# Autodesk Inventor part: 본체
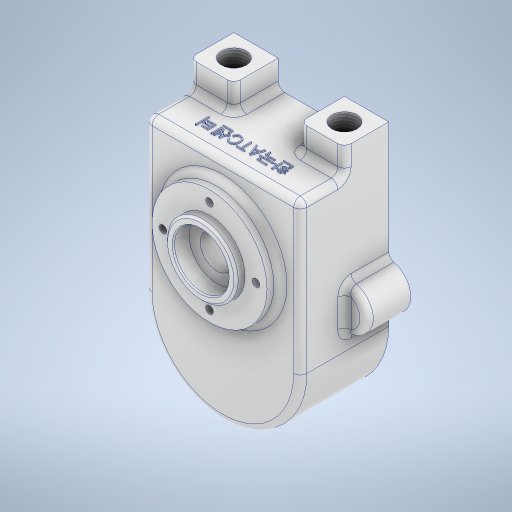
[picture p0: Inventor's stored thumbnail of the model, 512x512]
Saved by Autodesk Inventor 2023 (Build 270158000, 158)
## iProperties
Created: 2024-03
Part Number: 본체
Material: 알루미늄 6061
Document SubType Name: Modeling
Designer: asung
Density: 2.7 g/cm^3
Appearance: 알루미늄 - 평지
Author: asung
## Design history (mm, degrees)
sketch "스케치1" dims "d0" = 70
  geometry: L1 (0, 0)-(68, 0); L2 (35, 0)-(35, 68); L3 (35, 68)-(-35, 68); L4 (-35, 68)-(-35, 0); 3 further points
  constraints: 8 end point, 1 coincident, 1 horizontal, 1 horizontal alignment, 1 midpoint, 1 parallel, 1 perpendicular, 1 vertical alignment, 3 other
  dimensions: "d3" = 70 distance between parallel lines of L2 L4; "d4" = 68 distance of L2.start L2.end; "d5" = 68 distance from line of L4.end L3
extrude "돌출1" new body sketch "스케치1" distance "d6" = 40; taper "d7" = 0 deg
sketch "스케치2"
  geometry: L1 (-35, 68)-(-35, 0) reference; L2 (35, 0)-(35, 68) reference; L3 (35, 68)-(-35, 68) reference; C1 r 26 at (0, 33); A1 r 35 centre (0, 0) between (-35, 0) and (35, 0) reference; 2 further points
  constraints: 1 centre point, 1 midpoint, 1 vertical alignment
  dimensions: "d8" = 35 distance of point (0, 68) C1.centre; "d9" = 52 diameter of C1
extrude "돌출2" join sketch "스케치2" distance "d10" = 6; taper "d11" = 0 deg
sketch "스케치3"
  geometry: C1 r 26 at (0, 0) reference; C2 r 16 at (0, 0); 1 further point
  constraints: 1 centre point, 1 coincident
  dimensions: "d12" = 32 diameter of C2
extrude "돌출3" join sketch "스케치3" distance "d13" = 4; taper "d14" = 0 deg
sketch "스케치4"
  geometry: L1 (35, 68)-(35, 0) reference; L2 (-35, 68)-(35, 68) reference; L3 (-35, 0)-(-35, 68) reference; L4 (-15, 68)-(-15, 80); L5 (-15, 80)-(-35, 80); L6 (-35, 80)-(-35, 68); L7 (15, 68)-(15, 80); L8 (15, 80)-(35, 80); L9 (35, 80)-(35, 68); C1 r 29 at (0, 33) reference; A1 r 35 centre (0, 0) between (-35, 0) and (35, 0) reference; 1 further point
  constraints: 12 end point, 3 point on line, 2 horizontal, 2 parallel, 2 vertical
  dimensions: "d16" = 30 distance between parallel lines of L7 L4; "d17" = 20 distance of L7.end L8.end; "d18" = 12 distance between parallel lines of L2 L8
extrude "돌출4" join sketch "스케치4" distance "d19" = 20; taper "d20" = 0 deg
fillet "모깎기2" dims "d21" = 3
fillet "모깎기3" dims "d22" = 3
sketch "스케치5"
  geometry: L1 (0, 0)-(0, 33); L2 (-14, 11.314)-(-14, 21.686); L3 (14, 11.314)-(14, 21.686); C1 r 16 at (0, 33) reference; A1 r 18 centre (0, 33) between (14, 21.686) and (-14, 21.686); A2 r 18 centre (0, 0) between (-14, 11.314) and (14, 11.314); 1 further point
  constraints: 6 end point, 4 point on circle, 2 centre point, 2 coincident, 2 parallel, 1 vertical
  dimensions: "d26" = 33 distance of L1.start L1.end; "d30" = 36 diameter of A1; "d31" = 36 diameter of A2; "d32" = 28 distance between parallel lines of L3 L2; "d33" = 10.37258 distance of L3.start L3.end
extrude "돌출5" cut sketch "스케치5" distance "d34" = 20; taper "d35" = 0 deg
sketch "스케치6"
  geometry: L1 (-14, 11.314)-(-14, 21.686) reference; L2 (14, 21.686)-(14, 11.314) reference; L3 (35, 80)-(35, 0) reference; L4 (35, 80)-(15, 80) reference; L5 (15, 80)-(15, 71) reference; L6 (-12, 68)-(12, 68) reference; L7 (-15, 71)-(-15, 80) reference; L8 (-15, 80)-(-35, 80) reference; L9 (-35, 0)-(-35, 80) reference; C1 r 10 at (-35, 16.5); C2 r 10 at (35, 16.5); A1 r 18 centre (0, 33) between (14, 21.686) and (-14, 21.686) reference; A2 r 18 centre (0, 0) between (-14, 11.314) and (14, 11.314) reference; A3 r 3 centre (12, 71) between (12, 68) and (15, 71) reference; A4 r 3 centre (-12, 71) between (-15, 71) and (-12, 68) reference; A5 r 35 centre (0, 0) between (-35, 0) and (35, 0) reference; 7 further points
  constraints: 2 centre point, 2 horizontal alignment, 2 midpoint, 2 point on line
  dimensions: "d36" = 10 radius of C1; "d37" = 10 radius of C2
extrude "돌출6" join sketch "스케치6" distance "d38" = 20; taper "d39" = 0 deg
fillet "모깎기4" dims "d40" = 3
sketch "스케치7"
  geometry: A1 r 18 centre (0, 33) between (14, 21.686) and (-14, 21.686) reference; 2 further points
  constraints: 1 coincident
hole "구멍1" sketch "스케치7" at (0, 33) diameter "d41" = 15; stored, may be unused: countersink angle "d45" = 90 deg, drill point angle "d47" = 0 deg; dims "d42" = 8, "d43" = 20, "d44" = 10, "d46" = 40
sketch "스케치8"
  geometry: A1 r 18 centre (0, 0) between (-14, 11.314) and (14, 11.314) reference; 2 further points
  constraints: 1 coincident
hole "구멍2" sketch "스케치8" at (0, 0) diameter "d48" = 20; stored, may be unused: countersink angle "d52" = 90 deg, drill point angle "d54" = 0 deg; dims "d49" = 6, "d50" = 20, "d51" = 10, "d53" = 10
chamfer "모따기1" distance "d55" = 1; stored, may be unused: second distance "d56" = 2, angle "d57" = 45 deg
sketch "스케치9"
  geometry: 1 further point
node "작업 평면2"
sketch "스케치11"
  geometry: C1 r 13 at (0, 0) reference; 2 further points
  constraints: 1 coincident
hole "구멍3" sketch "스케치11" at (0, 0) diameter "d63" = 25; stored, may be unused: countersink angle "d67" = 90 deg, drill point angle "d69" = 0 deg; dims "d64" = 6, "d65" = 4, "d66" = 2, "d68" = 7.3
sketch "스케치12" dims "d73" = 42
  geometry: C1 r 16 at (0, 0) reference; C2 r 26 at (0, 0) reference; 3 further points
  constraints: 2 vertical alignment, 1 coincident, 2 other
hole "구멍4" sketch "스케치12" at (0, 21) diameter "d74" = 3.45873; stored, may be unused: countersink angle "d78" = 90 deg, drill point angle "d80" = 118 deg; dims "d75" = 8, "d76" = 4, "d77" = 2, "d79" = 10
sketch "스케치13"
  geometry: A1 r 10 centre (35, 16.5) between (37.308, 6.77) and (37.308, 26.23) reference; A2 r 10 centre (-35, 16.5) between (-37.308, 26.23) and (-37.308, 6.77) reference; 3 further points
  constraints: 2 coincident
hole "구멍5" sketch "스케치13" at (35, 16.5), (-35, 16.5) diameter "d84" = 4.45873; stored, may be unused: countersink angle "d88" = 90 deg, drill point angle "d90" = 118 deg; dims "d85" = 10, "d86" = 4, "d87" = 2, "d89" = 12
sketch "스케치14"
  geometry: L1 (-14, 11.314)-(-14, 21.686) reference; L2 (14, 21.686)-(14, 11.314) reference; L3 (35, 80)-(35, 29.149) reference; L4 (35, 80)-(15, 80) reference; L5 (15, 80)-(15, 71) reference; L6 (-12, 68)-(12, 68) reference; L7 (-15, 71)-(-15, 80) reference; L8 (-15, 80)-(-35, 80) reference; L9 (-35, 29.149)-(-35, 80) reference; L10 (-35, 0)-(-35, 3.851) reference; L11 (35, 3.851)-(35, 0) reference; C1 r 2.229 at (35, 16.5) reference; C2 r 2.229 at (-35, 16.5) reference; A1 r 18 centre (0, 33) between (14, 21.686) and (-14, 21.686) reference; A2 r 18 centre (0, 0) between (-14, 11.314) and (14, 11.314) reference; A3 r 3 centre (12, 71) between (12, 68) and (15, 71) reference; A4 r 3 centre (-12, 71) between (-15, 71) and (-12, 68) reference; A5 r 3 centre (-38, 29.149) between (-37.308, 26.23) and (-35, 29.149) reference; A6 r 10 centre (-35, 16.5) between (-37.308, 26.23) and (-37.308, 6.77) reference; A7 r 3 centre (-38, 3.851) between (-35, 3.851) and (-37.308, 6.77) reference; A8 r 35 centre (0, 0) between (-35, 0) and (35, 0) reference; A9 r 3 centre (38, 3.851) between (37.308, 6.77) and (35, 3.851) reference; A10 r 10 centre (35, 16.5) between (37.308, 6.77) and (37.308, 26.23) reference; A11 r 3 centre (38, 29.149) between (35, 29.149) and (37.308, 26.23) reference; 3 further points
  constraints: 2 vertical alignment
  dimensions: "d91" = 26 distance of A1.centre point (0, 59); "d92" = 26 distance of point (0, 0) point (0, -26)
hole "구멍6" sketch "스케치14" at (0, 59), (0, -26) diameter "d93" = 4.45873; stored, may be unused: countersink angle "d97" = 90 deg, drill point angle "d99" = 118 deg; dims "d94" = 10, "d95" = 4, "d96" = 2, "d98" = 12
sketch "스케치15"
  geometry: L1 (70, -20)-(53, -20) reference; L2 (70, 0)-(70, -20) reference; L3 (50, 0)-(70, 0) reference; L4 (50, 0)-(50, -17) reference; L5 (20, 0)-(20, -17) reference; L6 (0, 0)-(20, 0) reference; L7 (0, 0)-(0, -20) reference; L8 (17, -20)-(0, -20) reference; A1 r 3 centre (53, -17) between (50, -17) and (53, -20) reference; A2 r 3 centre (17, -17) between (17, -20) and (20, -17) reference; 3 further points
  constraints: 1 horizontal alignment
  dimensions: "d100" = 50 distance of point (60, -10) point (10, -10); "d101" = 10 distance from line of point (10, -10) L7; "d102" = 10 distance from line of L6 point (10, -10)
hole "구멍7" sketch "스케치15" at (10, -10), (60, -10) diameter "d103" = 10.5; stored, may be unused: countersink angle "d109" = 90 deg, drill point angle "d111" = 118 deg; dims "d104" = 11, "d105" = 0.62479, "d106" = 10.589, "d107" = 4, "d108" = 2, "d110" = 16
node "작업 평면1"
sketch "스케치17"
  geometry: L1 (-14, 21.686)-(-14, 11.314) reference; L2 (14, 11.314)-(14, 21.686) reference; L3 (-12, 68)-(12, 68) reference; L4 (15, 71)-(15, 80) reference; L5 (15, 80)-(19.362, 80) reference; L6 (19.362, 80)-(19.705, 69) reference; L7 (19.705, 69)-(19.75, 69) reference; L8 (19.75, 69)-(19.75, 64) reference; L9 (19.75, 64)-(25, 60.845) reference; L10 (25, 60.845)-(30.25, 64) reference; L11 (30.25, 64)-(30.25, 69) reference; L12 (30.25, 69)-(30.295, 69) reference; L13 (30.295, 69)-(30.638, 80) reference; L14 (30.638, 80)-(35, 80) reference; L15 (35, 80)-(35, 29.149) reference; L16 (35, 3.851)-(35, 0) reference; L17 (-35, 0)-(-35, 3.851) reference; L18 (-35, 29.149)-(-35, 80) reference; L19 (-35, 80)-(-30.638, 80) reference; L20 (-30.638, 80)-(-30.295, 69) reference; L21 (-30.295, 69)-(-30.25, 69) reference; L22 (-30.25, 69)-(-30.25, 64) reference; L23 (-30.25, 64)-(-25, 60.845) reference; L24 (-25, 60.845)-(-19.75, 64) reference; L25 (-19.75, 64)-(-19.75, 69) reference; L26 (-19.75, 69)-(-19.706, 69) reference; L27 (-19.706, 69)-(-19.362, 80) reference; L28 (-19.362, 80)-(-15, 80) reference; L29 (-15, 80)-(-15, 71) reference; L30 (-14, 11.314)-(-14, 21.686) reference; L31 (-19.75, 64)-(-30.25, 64) reference; L32 (-30.25, 64)-(-19.75, 64); L33 (25, 60.845)-(19.75, 64) reference; L34 (-25, 64)-(-25, 24.5); L35 (-14, 16.5)-(-17, 16.5); L36 (14, 21.686)-(14, 11.314) reference; L37 (19.75, 64)-(30.25, 64); L38 (25, 64)-(25, 24.5); L39 (14, 16.5)-(17, 16.5); L40 (28, 64)-(28, 24.5); L41 (17, 13.5)-(14, 13.5); L42 (22, 64)-(22, 24.5); L43 (17, 19.5)-(14, 19.5); L44 (-22, 64)-(-22, 24.5); L45 (-17, 19.5)-(-14, 19.5); L46 (-28, 64)-(-28, 24.5); L47 (-17, 13.5)-(-14, 13.5); C1 r 2.229 at (0, 59) reference; C2 r 2.229 at (0, -26) reference; C3 r 2.229 at (35, 16.5) reference; C4 r 2.229 at (-35, 16.5) reference; A1 r 18 centre (0, 0) between (-14, 11.314) and (14, 11.314) reference; A2 r 18 centre (0, 33) between (14, 21.686) and (-14, 21.686) reference; A3 r 3 centre (-12, 71) between (-15, 71) and (-12, 68) reference; A4 r 3 centre (12, 71) between (12, 68) and (15, 71) reference; A5 r 3 centre (38, 29.149) between (35, 29.149) and (37.308, 26.23) reference; A6 r 10 centre (35, 16.5) between (37.308, 6.77) and (37.308, 26.23) reference; A7 r 3 centre (38, 3.851) between (37.308, 6.77) and (35, 3.851) reference; A8 r 35 centre (0, 0) between (-35, 0) and (35, 0) reference; A9 r 3 centre (-38, 3.851) between (-35, 3.851) and (-37.308, 6.77) reference; A10 r 10 centre (-35, 16.5) between (-37.308, 26.23) and (-37.308, 6.77) reference; A11 r 3 centre (-38, 29.149) between (-37.308, 26.23) and (-35, 29.149) reference; A12 r 8 centre (-17, 24.5) between (-25, 24.5) and (-17, 16.5); A13 r 8 centre (17, 24.5) between (17, 16.5) and (25, 24.5); A14 r 11 centre (17, 24.5) between (17, 13.5) and (28, 24.5); A15 r 5 centre (17, 24.5) between (17, 19.5) and (22, 24.5); A16 r 5 centre (-17, 24.5) between (-22, 24.5) and (-17, 19.5); A17 r 11 centre (-17, 24.5) between (-28, 24.5) and (-17, 13.5); 9 further points
  constraints: 28 end point, 12 point on circle, 6 centre point, 4 tangent, 3 midpoint, 3 perpendicular, 2 horizontal, 2 vertical, 1 equal radius, 1 vertical alignment, 8 other
  dimensions: "d123" = 8 radius of A12 (derived); "d124" = 3 distance between parallel lines of L38 L40; "d125" = 3 distance between parallel lines of L38 L42; "d126" = 3 distance between parallel lines of L34 L44; "d127" = 3 distance between parallel lines of L34 L46
extrude "돌출8" cut sketch "스케치17" stored distance "d128" = 6; taper "d129" = 0 deg
fillet "모깎기6" dims "d130" = 3
fillet "모깎기7" dims "d131" = 3
fillet "모깎기8" dims "d132" = 3
sketch "스케치18"
  geometry: L1 (24, 0)-(0, 0) reference; 3 further points
  constraints: 1 midpoint, 1 vertical alignment, 1 other
  dimensions: "d133" = 30 distance from line of L1 point (12, -30)
feature "엠보싱1" sketch "스케치18" dims "d134" = 0.5, "d135" = 0
fillet "모깎기9" dims "d136" = 3
chamfer "모따기3" distance "d137" = 1; stored, may be unused: second distance "d138" = 2, angle "d139" = 30 deg
chamfer "모따기4" distance "d140" = 0.7; stored, may be unused: second distance "d141" = 2, angle "d142" = 30 deg
fillet "모깎기10" dims "d143" = 3
sketch "스케치19"
  geometry: L1 (11, 20)-(10, 21) reference; L2 (10, 21)-(10, 30) reference; L3 (10, 30)-(-10, 30) reference; L4 (-10, 30)-(-10, 21) reference; L5 (-10, 21)-(-11, 20) reference; L6 (-11, 20)-(-18, 20) reference; L7 (-18, 20)-(-18, 0) reference; L8 (-18, 0)-(-23.771, 0) reference; L9 (-23.771, 0)-(-23.771, 12) reference; L10 (-23.771, 12)-(-26, 13.34) reference; L11 (-26, 13.34)-(-28.229, 12) reference; L12 (-28.229, 12)-(-28.229, 0) reference; L13 (-28.229, 0)-(-35, 0) reference; L14 (-35, 0)-(-35, 37) reference; L15 (-32, 40)-(4, 40) reference; L16 (7, 43)-(7, 46) reference; L17 (7, 46)-(10.271, 46) reference; L18 (10.271, 46)-(10.271, 36) reference; L19 (10.271, 36)-(12, 34.961) reference; L20 (12, 34.961)-(13.729, 36) reference; L21 (13.729, 36)-(13.729, 46) reference; L22 (13.729, 46)-(17, 46) reference; L23 (17, 46)-(17, 49) reference; L24 (17, 49)-(18, 50) reference; L25 (18, 50)-(20.096, 50) reference; L26 (20.096, 50)-(20.5, 49.3) reference; L27 (20.5, 49.3)-(20.5, 42.7) reference; L28 (20.5, 42.7)-(25.5, 42.7) reference; L29 (25.5, 42.7)-(25.5, 30) reference; L30 (25.5, 30)-(23, 30) reference; L31 (23, 30)-(23, 21) reference; L32 (23, 21)-(22, 20) reference; L33 (22, 20)-(11, 20) reference; L34 (51, 20)-(44, 20) reference; L35 (44, 20)-(43, 21) reference; L36 (43, 21)-(43, 30) reference; L37 (43, 30)-(40.5, 30) reference; L38 (40.5, 30)-(40.5, 42.7) reference; L39 (40.5, 42.7)-(45.5, 42.7) reference; L40 (45.5, 42.7)-(45.5, 49.3) reference; L41 (45.5, 49.3)-(45.904, 50) reference; L42 (45.904, 50)-(48, 50) reference; L43 (48, 50)-(49, 49) reference; L44 (49, 49)-(49, 46) reference; L45 (49, 46)-(52.271, 46) reference; L46 (52.271, 46)-(52.271, 36) reference; L47 (52.271, 36)-(54, 34.961) reference; L48 (54, 34.961)-(55.729, 36) reference; L49 (55.729, 36)-(55.729, 46) reference; L50 (55.729, 46)-(59, 46) reference; L51 (59, 46)-(59, 43) reference; L52 (62, 40)-(65, 40) reference; L53 (68, 37)-(68, 32.385) reference; L54 (68, 32.385)-(68.5, 32.385) reference; L55 (68.5, 32.385)-(68.5, 31.971) reference; L56 (68.5, 31.971)-(68, 31.971) reference; L57 (68, 31.971)-(68, 0) reference; L58 (68, 0)-(61.229, 0) reference; L59 (61.229, 0)-(61.229, 12) reference; L60 (61.229, 12)-(59, 13.34) reference; L61 (59, 13.34)-(56.771, 12) reference; L62 (56.771, 12)-(56.771, 0) reference; L63 (56.771, 0)-(51, 0) reference; L64 (51, 0)-(51, 20) reference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; A1 r 3 centre (-32, 37) between (-32, 40) and (-35, 37) reference; A2 r 3 centre (4, 43) between (4, 40) and (7, 43) reference; A3 r 3 centre (62, 43) between (59, 43) and (62, 40) reference; A4 r 3 centre (65, 37) between (68, 37) and (65, 40) reference; 1 further point
  constraints: 4 end point, 3 point on line, 1 other
  dimensions: "d144" = 120 deg angle of L67 L65; "d145" = 14 distance of L65.start L67.end
revolve "회전2" sketch "스케치19" stored, may be unused: angle "d146" = 90 deg
feature "٣耀٥耀٧耀٩耀٫耀٭耀ٯ耀ٱ耀" dims "d0" = 70, "d3" = 70, "d4" = 68, "d5" = 68, "d6" = 40, "d7" = 0, "d8" = 35, "d9" = 52, "d10" = 6, "d11" = 0, "d12" = 32, "d13" = 4, "d14" = 0, "d16" = 30, "d17" = 20, "d18" = 12, "d19" = 20, "d20" = 0, "d21" = 3, "d22" = 3, "d23" = 36, "d24" = 14, "d25" = 14, "d26" = 33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
node "솔리드1"
pattern_circular "원형 패턴1" dims angle "d82" = 360 deg
node "투영된 루프1"
node "투영된 루프2"
node "투영된 루프3"
node "투영된 루프4"
node "투영된 루프5"
node "투영된 루프6"
node "투영된 루프7"
node "투영된 루프8"
node "절단 모서리 투영3"
node "절단 모서리 투영4"
feature "A9D066F2-1C7D-4E18-AEED-F7BC21143FA4" dims "d41" = 15, "d42" = 8, "d43" = 20, "d44" = 10, "d45" = 90 deg, "d46" = 40, "d47" = 0
